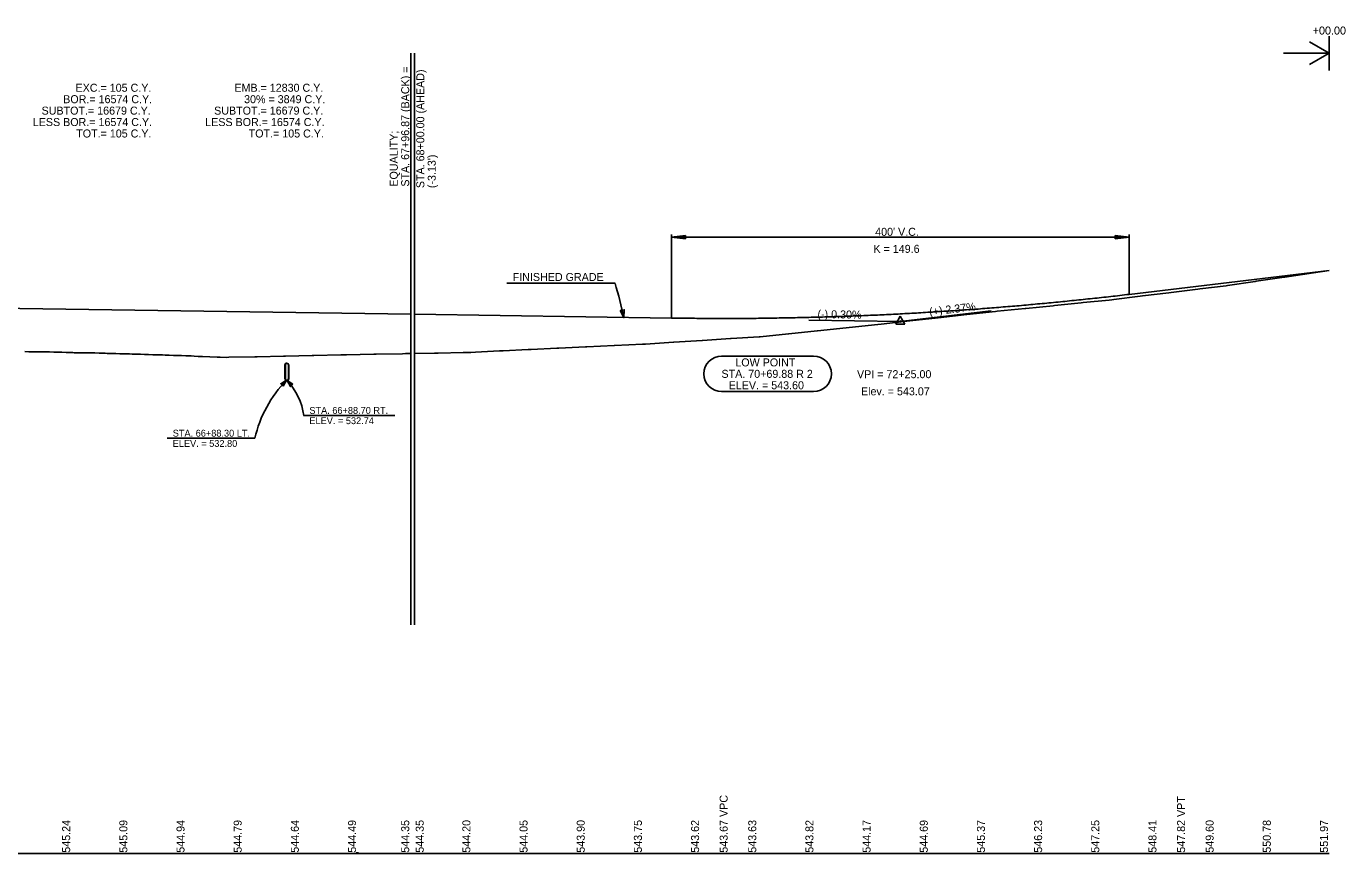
# Model space of a CAD drawing. Extents: x 49922 to 52614, y 49991 to 60509.
# Drawn here: x 51461 to 52614, y 52500 to 53223 of the extents above; entities that cross this region are included whole.
import ezdxf

# ---------------------------------------------------------------- set-up
doc = ezdxf.new("R2010")
doc.units = 0
for name, color, linetype in [('RD_DDB_GradeTX', 7, 'Continuous'), ('RD_DDB_Profile_EX', 7, 'Continuous'), ('RD_DDB_Profile_Lbl', 7, 'Continuous'), ('RD_DDB_Profile_PR', 7, 'Continuous'), ('RD_DDB_StripGrade', 7, 'Continuous'), ('RD_DDB_VCLbl', 7, 'Continuous'), ('RD_GPK_Profile_Cell', 7, 'Continuous'), ('RD_Sketch2', 7, 'Continuous'), ('RD_TX_Profile', 7, 'Continuous')]:
    doc.layers.add(name, color=color, linetype=linetype)

msp = doc.modelspace()

# ---------------------------------------------------------------- linework, layer by layer
at = {"layer": 'RD_DDB_GradeTX'}
for p, q in [((52145, 52966.6), (52225, 52965.4)), ((52221, 52963.1), (52225, 52969.9)), ((52304.4, 52974.8), (52225, 52965.4)), ((52225, 52969.9), (52229, 52963.1)), ((52221, 52963.1), (52229, 52963.1))]:
    msp.add_line(p, q, dxfattribs=at)
msp.add_circle((52225, 52965.4), 0.529, dxfattribs=at)
at = {"layer": 'RD_DDB_Profile_EX'}
for points in [[(51800, 52937.4), (51817.6, 52937.8), (51820.9, 52937.8), (51842.6, 52938.3), (51843.6, 52938.3), (51849.5, 52938.4), (51853.4, 52938.6), (51874.5, 52939.6), (51877.8, 52939.8), (51899.6, 52940.8), (51902.1, 52940.9), (51924.6, 52942), (51926.4, 52942.1), (51949.6, 52943.2), (51950.7, 52943.2), (51974.7, 52944.4), (51975, 52944.4), (51987.6, 52945), (51999.4, 52945.5), (51999.7, 52945.5), (52002, 52945.6), (52026.6, 52947.2), (52027, 52947.2), (52051.6, 52948.8), (52052, 52948.8), (52076.6, 52950.4), (52077, 52950.5), (52101.6, 52952), (52102, 52952.1), (52102.5, 52952.1), (52127.1, 52954.7), (52127.5, 52954.7), (52152.2, 52957.3), (52152.5, 52957.3), (52177.5, 52959.9), (52202.5, 52962.5), (52208.2, 52963.1), (52233.2, 52965.9), (52258.2, 52968.6), (52283.2, 52971.4), (52308.1, 52974.1), (52309.8, 52974.3), (52334.1, 52976.7), (52334.9, 52976.8), (52358.6, 52979.2), (52359.9, 52979.3), (52383, 52981.7), (52384.9, 52981.9), (52407.5, 52984.1), (52410, 52984.4), (52411.8, 52984.6), (52434.6, 52987.4), (52436.8, 52987.7), (52459.9, 52990.5), (52461.8, 52990.8), (52485.2, 52993.7), (52486.8, 52993.9), (52510, 52996.7), (52511.2, 52996.9), (52535.3, 53000.4), (52536.2, 53000.5), (52560.6, 53004.1), (52561.2, 53004.2), (52586.3, 53007.8), (52600, 53009.9)], [(51459.3, 52939), (51462.9, 52938.9), (51463.7, 52938.9), (51466.5, 52938.9), (51470.1, 52938.9), (51472.5, 52938.8), (51474, 52938.8), (51476.2, 52938.8), (51477.4, 52938.8), (51481, 52938.7), (51484.6, 52938.6), (51488.2, 52938.6), (51489.6, 52938.6), (51491.8, 52938.5), (51495.4, 52938.4), (51499, 52938.2), (51501.2, 52938.2), (51502.6, 52938.1), (51506.2, 52938.1), (51509.9, 52938), (51513.5, 52938), (51517.1, 52937.9), (51519.1, 52937.9), (51520.7, 52937.9), (51524.3, 52937.7), (51526.2, 52937.7), (51527.9, 52937.6), (51528.9, 52937.6), (51529.7, 52937.6), (51531.5, 52937.5), (51535.1, 52937.4), (51538.8, 52937.3), (51542.4, 52937.2), (51546, 52937.1), (51549.6, 52937), (51551, 52937), (51553.2, 52936.9), (51554.7, 52936.9), (51556.8, 52936.8), (51560.4, 52936.7), (51564, 52936.6), (51567.6, 52936.5), (51571.3, 52936.3), (51574.9, 52936.2), (51577.6, 52936.1), (51578.5, 52936.1), (51579.7, 52936.1)], [(51579.7, 52936.1), (51582.1, 52936), (51585.7, 52935.8), (51589.3, 52935.7), (51592.9, 52935.6), (51596.5, 52935.5), (51600.1, 52935.3), (51603, 52935.2), (51603.8, 52935.2), (51604.7, 52935.2), (51607.4, 52935.1), (51611, 52934.9), (51614.6, 52934.8), (51627.6, 52934.3), (51629.7, 52934.2), (51630.1, 52934.2), (51635.5, 52934), (51637.8, 52934.1), (51660.5, 52934.5), (51662.6, 52934.6), (51685.5, 52935.1), (51687.4, 52935.1), (51710.5, 52935.6), (51712.1, 52935.6), (51735.8, 52936.1), (51739.6, 52936.2), (51740.8, 52936.2), (51764.5, 52936.7), (51766.5, 52936.8), (51789.5, 52937.2), (51792.2, 52937.3), (51796.9, 52937.4)]]:
    msp.add_lwpolyline(points, dxfattribs=at)
at = {"layer": 'RD_DDB_Profile_PR'}
for p, q in [((52425, 52989.1), (52600, 53009.9)), ((50750, 52987.4), (51796.9, 52971.7)), ((51800, 52971.7), (52025, 52968.4))]:
    msp.add_line(p, q, dxfattribs=at)
msp.add_spline([(52025, 52968.4), (52033, 52968.2), (52041, 52968.2), (52049, 52968.1), (52057, 52968), (52065, 52968), (52073, 52968), (52081, 52968), (52089, 52968.1), (52097, 52968.1), (52105, 52968.2), (52113, 52968.3), (52121, 52968.5), (52129, 52968.6), (52137, 52968.8), (52145, 52969), (52153, 52969.2), (52161, 52969.4), (52169, 52969.7), (52177, 52969.9), (52185, 52970.2), (52193, 52970.5), (52201, 52970.9), (52209, 52971.2), (52217, 52971.6), (52225, 52972), (52233, 52972.5), (52241, 52972.9), (52249, 52973.4), (52257, 52973.9), (52265, 52974.4), (52273, 52974.9), (52281, 52975.5), (52289, 52976), (52297, 52976.6), (52305, 52977.3), (52313, 52977.9), (52321, 52978.6), (52329, 52979.2), (52337, 52979.9), (52345, 52980.7), (52353, 52981.4), (52361, 52982.2), (52369, 52983), (52377, 52983.8), (52385, 52984.6), (52393, 52985.5), (52401, 52986.3), (52409, 52987.2), (52417, 52988.1), (52425, 52989.1)], degree=3, dxfattribs=at)
at = {"layer": 'RD_DDB_VCLbl'}
for p, q in [((51796.9, 52700), (51796.9, 53200)), ((51800, 52700), (51800, 53200)), ((52025, 53041.6), (52025, 52968.4)), ((52037, 53040.6), (52025, 53039.1)), ((52025, 53039.1), (52425, 53039.1)), ((52025, 53039.1), (52037, 53037.6)), ((52037, 53037.6), (52037, 53040.6)), ((52425, 53039.1), (52413, 53040.6)), ((52413, 53040.6), (52413, 53037.6)), ((52413, 53037.6), (52425, 53039.1)), ((52425, 53041.6), (52425, 52989.1)), ((51749, 52500.8), (51751.1, 52500.8))]:
    msp.add_line(p, q, dxfattribs=at)
at = {"layer": 'RD_GPK_Profile_Cell'}
msp.add_line((50000, 52500), (52600, 52500), dxfattribs=at)
at = {"layer": 'RD_Sketch2'}
for p, q in [((51686.8, 52915.5), (51686.8, 52927.5)), ((51687.2, 52915.2), (51687.2, 52927.2)), ((51689.8, 52915.5), (51689.8, 52927.5)), ((51690.2, 52915.2), (51690.2, 52927.2))]:
    msp.add_line(p, q, dxfattribs=at)
for centre, start, end in [((51688.3, 52927.5), 360, 180), ((51688.7, 52927.2), 360, 180), ((51688.3, 52915.5), 180, 0), ((51688.7, 52915.2), 180, 0)]:
    msp.add_arc(centre, 1.5, start, end, dxfattribs=at)
at = {"layer": 'RD_TX_Profile'}
for p, q in [((52582.7, 53210), (52600, 53200)), ((52600, 53215), (52600, 53185)), ((52560, 53200), (52600, 53200)), ((52582.7, 53190), (52600, 53200)), ((51975.6, 52998.8), (51881, 52998.8)), ((52149.2, 52935.1), (52068.7, 52935.1)), ((52068.7, 52904.1), (52149.2, 52904.1)), ((51783, 52883.1), (51703.2, 52883.1)), ((51660.5, 52863.2), (51583.7, 52863.2))]:
    msp.add_line(p, q, dxfattribs=at)
for points in [[(51980.1, 52974.9), (51983.2, 52968.6), (51983.6, 52975.6)], [(51685.3, 52908.8), (51688.3, 52914), (51683.1, 52911)], [(51693.8, 52910.6), (51688.7, 52913.7), (51691.6, 52908.4)]]:
    msp.add_lwpolyline(points, close=True, dxfattribs=at)
for centre, radius, start, end in [((51680.1, 52908.1), 309, 11.2888, 17.0526), ((52068.7, 52919.6), 15.5, 90, 270), ((52149.2, 52919.6), 15.5, 270, 90), ((51762.3, 52840.6), 104.2, 135.2071, 167.4766), ((51649.2, 52876.2), 54.5, 7.246, 43.5061)]:
    msp.add_arc(centre, radius, start, end, dxfattribs=at)

# ---------------------------------------------------------------- texts
at = {"layer": 'RD_DDB_GradeTX'}
for s, rotation, p in [('(+) 2.37%', 6.7684, (52250.7, 52970.4)), ('(-) 0.30%', 359.1406, (52152.5, 52968.4))]:
    msp.add_text(s, height=7, rotation=rotation, dxfattribs=at).set_placement(p)
at = {"layer": 'RD_DDB_Profile_Lbl'}
for s, p in [('VPI = 72+25.00', (52187.1, 52915.8)), ('Elev. = 543.07', (52190.6, 52900.8))]:
    msp.add_text(s, height=7, dxfattribs=at).set_placement(p)
at = {"layer": 'RD_DDB_StripGrade'}
for s, p in [('543.67 VPC', (52074, 52500.8)), ('547.82 VPT', (52474, 52500.8)), ('545.24', (51499, 52500.8)), ('545.09', (51549, 52500.8)), ('544.94', (51599, 52500.8)), ('544.79', (51649, 52500.8)), ('544.64', (51699, 52500.8)), ('544.49', (51749, 52500.8)), ('544.35', (51795.5, 52500.8)), ('544.35', (51808.2, 52500.8)), ('544.20', (51849, 52500.8)), ('544.05', (51899, 52500.8)), ('543.90', (51949, 52500.8)), ('543.75', (51999, 52500.8)), ('543.62', (52049, 52500.8)), ('543.63', (52099, 52500.8)), ('543.82', (52149, 52500.8)), ('544.17', (52199, 52500.8)), ('544.69', (52249, 52500.8)), ('545.37', (52299, 52500.8)), ('546.23', (52349, 52500.8)), ('547.25', (52399, 52500.8)), ('548.41', (52449, 52500.8)), ('549.60', (52499, 52500.8)), ('550.78', (52549, 52500.8)), ('551.97', (52599, 52500.8))]:
    msp.add_text(s, height=7, rotation=90, dxfattribs=at).set_placement(p)
at = {"layer": 'RD_DDB_VCLbl'}
for s, p in [("400' V.C.", (52203, 53040.3)), ('K = 149.6', (52201.5, 53025.4))]:
    msp.add_text(s, height=7, dxfattribs=at).set_placement(p)
at = {"layer": 'RD_TX_Profile'}
for s, height, p in [('+00.00', 7.06, (52585.6, 53216.3)), ('BOR.= 16574 C.Y.', 7, (51492.9, 53156.3)), ('EXC.= 105 C.Y.', 7, (51503.7, 53166.3)), ('EMB.= 12830 C.Y.', 7, (51642.6, 53166.3)), ('30% = 3849 C.Y.', 7, (51651.1, 53156.3)), ('SUBTOT.= 16679 C.Y.', 7, (51474, 53146.3)), ('SUBTOT.= 16679 C.Y.', 7, (51624.9, 53146.3)), ('LESS BOR.= 16574 C.Y.', 7, (51466.3, 53136.3)), ('LESS BOR.= 16574 C.Y.', 7, (51617.1, 53136.3)), ('TOT.= 105 C.Y.', 7, (51504.3, 53126.3)), ('TOT.= 105 C.Y.', 7, (51655.1, 53126.3)), ('FINISHED GRADE', 7, (51886, 53000.8)), ('STA. 66+88.70 RT.', 6, (51708.2, 52884.6)), ('ELEV. = 532.74', 6, (51708.2, 52875.6)), ('STA. 66+88.30 LT.', 6, (51588.7, 52864.7)), ('ELEV. = 532.80', 6, (51588.7, 52855.7))]:
    msp.add_text(s, height=height, dxfattribs=at).set_placement(p)
for s, rotation, p in [('STA. 67+96.87 (BACK) =', 90, (51795.5, 53083.3)), ('STA. 68+00.00 (AHEAD)', 90, (51808.7, 53082)), ('EQUALITY;', 90, (51785.5, 53083.3)), ("(-3.13')", 90, (51818.7, 53082)), ('LOW POINT', 360, (52080.7, 52926.1)), ('STA. 70+69.88 R 2', 360, (52068.6, 52916.1)), ('ELEV. = 543.60', 360, (52074.9, 52906.1))]:
    msp.add_text(s, height=7, rotation=rotation, dxfattribs=at).set_placement(p)

doc.saveas('drawing.dxf')
